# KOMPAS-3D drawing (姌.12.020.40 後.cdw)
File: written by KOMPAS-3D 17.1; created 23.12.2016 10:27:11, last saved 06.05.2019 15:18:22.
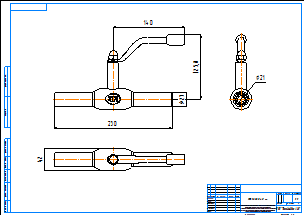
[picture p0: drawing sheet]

Sheet 1: A2, landscape

Title block, sheet 1: name: КШ.12.020.40 сс; material: Внимание! Данный продукт является объектом авторского права ООО «Торговый Дом АДЛ». / Запрещается изменение, копирование, распространение / (в том числе путем копирования на другие сайты и ресурсы в Интернете) / или любое иное использование информации и объектов без предварительного / согласия правообладателя (ООО «Торговый Дом АДЛ»).; sheets: 1; organisation: ООО "Торговый дом АДЛ"; sheet format: A2; stored path: C:\Users\tra\Desktop\2д чертежи\Шаровые краны БИВАЛ\КШ_Бивал_серия_11_12\KOMPAS_2D\КШ.12.020.40 сс.cdw

Views: Вид 1, Проекционный вид 2, Проекционный вид 3
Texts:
  Klimkovich
  ADL
Dimensions and other numbers on the sheet: 230; 27; 125,8; 140; 21; 42; 1:1; 1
